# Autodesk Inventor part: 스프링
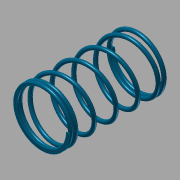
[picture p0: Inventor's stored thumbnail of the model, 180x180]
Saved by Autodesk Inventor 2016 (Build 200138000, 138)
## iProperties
Created: 2019-02
Part Number: 스프링
Material: 강철
Document SubType Name: Modeling
Designer: mduedu
Density: 2.18 g/cm^3
Appearance: 하늘색 짙음
CustomPartVersion: 1
Author: mduedu
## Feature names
1. Main Coil Feature(R)
2. Coil  Start Transition 2(R)
3. Coil  Start Transition 3(R)
4. Coil  Start Transition 4(R)
5. Plain Ends Cut  2(R) [Extrusion]
6. Main Coil Feature(L)
7. Cut Plain Ends Cut 1(L) [Extrusion]
8. Cut Plain Ends Cut 2(L) [Extrusion]
## Parameters: d0 = 0.25 mm, da_d = 1 mm, da_D2 = 13 mm, da_ti = 5.79943 mm, da_nz1 = 15 mm, spiral_Angle = 1.31102 mm, d2 = 5.79943 mm, d4 = 32.5 mm, d5 = 0, d6 = 90 deg, d7 = 90 deg, d8 = 0, d9 = 0, d12 = 3.09988 mm, d13 = -4.05199 mm, d14 = 1 mm, d15 = 0, d16 = 4.59957 mm, d18 = 2.5 mm, d19 = 0, d20 = 90 deg, d21 = 90 deg, d22 = 0, d23 = 0, d24 = 3.39971 mm, d26 = 2.5 mm, d27 = 0, d28 = 90 deg, d29 = 90 deg, d30 = 0, d31 = 0, d32 = 2.19986 mm, d34 = 2.5 mm, d35 = 0, d36 = 90 deg, d37 = 90 deg, d38 = 0, d39 = 0, d40 = 1 mm, d42 = 2.5 mm, d43 = 0, d44 = 90 deg, d45 = 90 deg, d46 = 0, d47 = 0, d48 = 4.59957 mm, d50 = 1.875 mm, d51 = 0, d52 = 90 deg, d53 = 90 deg, d54 = 0, d55 = 0, d56 = 3.39971 mm, d58 = 1.875 mm, d59 = 0, d60 = 90 deg, d61 = 90 deg, d62 = 0, d63 = 0, d64 = 2.19986 mm, d66 = 1.875 mm, d67 = 0, d68 = 90 deg, d69 = 90 deg, d70 = 0, d71 = 0, d72 = 1 mm, d74 = 1.875 mm, d75 = 0, d76 = 90 deg, d77 = 90 deg, d78 = 0, d79 = 0, End_Pitch = 1.00866 mm, d82 = 15 mm, d83 = 0, d84 = 90 deg, d85 = 90 deg, d86 = 0, d87 = 0, d88 = 1.00866 mm, d91 = 0, d92 = 90 deg, d93 = 90 deg, d94 = 0, d95 = 0, d96 = 15 mm, d97 = 1.00866 mm, d98 = 0, d99 = 15 mm, d100 = 1.00866 mm, d101 = 0, d102 = 0, d103 = 0, d104 = 0, d105 = 0, d106 = 0, d108 = 0, d112 = 0, d113 = 0, d114 = 0, const_zero = 0, Not_rightdir = 0, d121 = 0.26078 mm, d131 = 0, d132 = 0, d133 = 0, d134 = 0, d135 = 0.25 mm, d137 = 5.79943 mm, d139 = 32.5 mm, d140 = 0, d141 = 90 deg, d142 = 90 deg, d143 = 0, d144 = 0, d145 = 3.09988 mm, d146 = -4.05199 mm, d147 = 0.26078 mm, d148 = 0.00862 mm, d149 = 1 mm, d150 = 0, d151 = 0, d152 = 4.59957 mm, d154 = 2.5 mm, d155 = 0, d156 = 90 deg, d157 = 90 deg, d158 = 0, d159 = 0, d160 = 3.39971 mm, d162 = 2.5 mm, d163 = 0, d164 = 90 deg, d165 = 90 deg, d166 = 0, d167 = 0, d168 = 2.19986 mm, d170 = 2.5 mm, d171 = 0, d172 = 90 deg, d173 = 90 deg, d174 = 0, d175 = 0, d176 = 1 mm, d178 = 2.5 mm, d179 = 0, d180 = 90 deg, d181 = 90 deg, d182 = 0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
